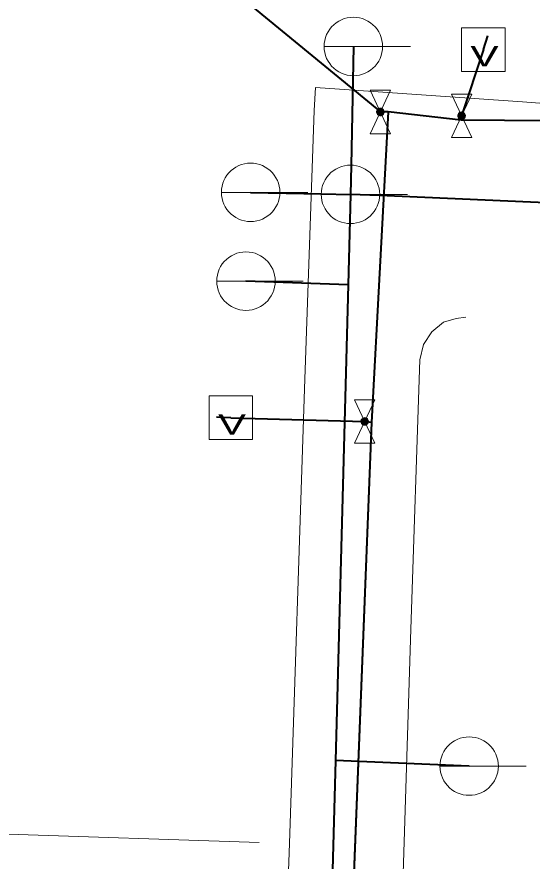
# Model space of a CAD drawing. Extents: x -968691 to -140888, y -1376050 to -879856.
# Drawn here: x -646127.69 to -646109.94, y -1062448.94 to -1062419.83 of the extents above; entities that cross this region are included whole.
import ezdxf
from ezdxf.enums import TextEntityAlignment as Align

# ---------------------------------------------------------------- set-up
doc = ezdxf.new("R2010")
doc.units = 0
doc.header["$LTSCALE"] = 4.8
doc.linetypes.add('DOTTED', pattern=[1.5, 0.3, -1.2])
doc.linetypes.add('LONG_DASHED', pattern=[7.5, 6, -1.5])
doc.layers.add('1', color=7, linetype='Continuous', lineweight=13)

msp = doc.modelspace()

# ---------------------------------------------------------------- hatches: boundary and pattern name
at = {"layer": '1'}
for points in [[(-646115.038, -1062423.11), (-646115.04, -1062423.086), (-646115.047, -1062423.063), (-646115.057, -1062423.041), (-646115.071, -1062423.022), (-646115.089, -1062423.005), (-646115.109, -1062422.992), (-646115.132, -1062422.983), (-646115.155, -1062422.979), (-646115.179, -1062422.978), (-646115.203, -1062422.982), (-646115.226, -1062422.99), (-646115.247, -1062423.002), (-646115.265, -1062423.018), (-646115.28, -1062423.037), (-646115.292, -1062423.058), (-646115.299, -1062423.081), (-646115.302, -1062423.105), (-646115.301, -1062423.129), (-646115.295, -1062423.152), (-646115.285, -1062423.174), (-646115.272, -1062423.194), (-646115.255, -1062423.211), (-646115.235, -1062423.225), (-646115.213, -1062423.235), (-646115.19, -1062423.241), (-646115.166, -1062423.242), (-646115.142, -1062423.239), (-646115.119, -1062423.232), (-646115.098, -1062423.221), (-646115.079, -1062423.206), (-646115.063, -1062423.187), (-646115.051, -1062423.167), (-646115.042, -1062423.144), (-646115.038, -1062423.12)], [(-646112.238, -1062423.24), (-646112.24, -1062423.216), (-646112.247, -1062423.193), (-646112.257, -1062423.171), (-646112.271, -1062423.152), (-646112.289, -1062423.135), (-646112.309, -1062423.122), (-646112.332, -1062423.113), (-646112.355, -1062423.109), (-646112.379, -1062423.108), (-646112.403, -1062423.112), (-646112.426, -1062423.12), (-646112.447, -1062423.132), (-646112.465, -1062423.148), (-646112.48, -1062423.167), (-646112.492, -1062423.188), (-646112.499, -1062423.211), (-646112.502, -1062423.235), (-646112.501, -1062423.259), (-646112.495, -1062423.282), (-646112.485, -1062423.304), (-646112.472, -1062423.324), (-646112.455, -1062423.341), (-646112.435, -1062423.355), (-646112.413, -1062423.365), (-646112.39, -1062423.371), (-646112.366, -1062423.372), (-646112.342, -1062423.369), (-646112.319, -1062423.362), (-646112.298, -1062423.351), (-646112.279, -1062423.336), (-646112.263, -1062423.317), (-646112.251, -1062423.297), (-646112.242, -1062423.274), (-646112.238, -1062423.25)], [(-646115.578, -1062433.78), (-646115.58, -1062433.756), (-646115.587, -1062433.733), (-646115.597, -1062433.711), (-646115.611, -1062433.692), (-646115.629, -1062433.675), (-646115.649, -1062433.662), (-646115.672, -1062433.653), (-646115.695, -1062433.649), (-646115.719, -1062433.648), (-646115.743, -1062433.652), (-646115.766, -1062433.66), (-646115.787, -1062433.672), (-646115.805, -1062433.688), (-646115.82, -1062433.707), (-646115.832, -1062433.728), (-646115.839, -1062433.751), (-646115.842, -1062433.775), (-646115.841, -1062433.799), (-646115.835, -1062433.822), (-646115.825, -1062433.844), (-646115.812, -1062433.864), (-646115.795, -1062433.881), (-646115.775, -1062433.895), (-646115.753, -1062433.905), (-646115.73, -1062433.911), (-646115.706, -1062433.912), (-646115.682, -1062433.909), (-646115.659, -1062433.902), (-646115.638, -1062433.891), (-646115.619, -1062433.876), (-646115.603, -1062433.857), (-646115.591, -1062433.837), (-646115.582, -1062433.814), (-646115.578, -1062433.79)]]:
    msp.add_hatch(color=256, dxfattribs=at).paths.add_polyline_path(points)

# ---------------------------------------------------------------- linework, layer by layer
at = {"layer": '1', "linetype": 'LONG_DASHED', "lineweight": 40}
for p, q in [((-646120.07, -1062419.07), (-646115.17, -1062423.11)), ((-646111.62, -1062420.96), (-646112.37, -1062423.24)), ((-646114.9, -1062423.11), (-646115.17, -1062423.11)), ((-646112.39, -1062423.39), (-646112.37, -1062423.24)), ((-646116.2, -1062425.95), (-646116.283, -1062429.074)), ((-646115.201, -1062425.99), (-646116.2, -1062425.95)), ((-646106.61, -1062426.36), (-646115.201, -1062425.99)), ((-646116.283, -1062429.074), (-646119.8, -1062428.94)), ((-646116.283, -1062429.074), (-646116.721, -1062445.47)), ((-646120.32, -1062433.65), (-646115.71, -1062433.78)), ((-646115.47, -1062433.81), (-646116.12, -1062450.33)), ((-646115.47, -1062433.81), (-646115.71, -1062433.78)), ((-646112.11, -1062445.66), (-646116.721, -1062445.47))]:
    msp.add_line(p, q, dxfattribs=at)
at = {"layer": '1'}
for p, q in [((-646120.07, -1062419.07), (-646115.17, -1062423.11)), ((-646111.62, -1062420.96), (-646111.464, -1062420.485)), ((-646117.108, -1062420.85), (-646114.132, -1062420.85)), ((-646111.62, -1062420.96), (-646112.37, -1062423.24)), ((-646117.453, -1062423.059), (-646117.41, -1062422.27)), ((-646117.782, -1062432.654), (-646117.453, -1062423.059)), ((-646114.9, -1062423.11), (-646115.17, -1062423.11)), ((-646112.39, -1062423.39), (-646112.37, -1062423.24)), ((-646120.648, -1062425.88), (-646117.672, -1062425.88)), ((-646117.208, -1062425.95), (-646114.232, -1062425.95)), ((-646115.201, -1062425.99), (-646116.2, -1062425.95)), ((-646106.61, -1062426.36), (-646115.201, -1062425.99)), ((-646120.808, -1062428.94), (-646117.832, -1062428.94)), ((-646116.283, -1062429.074), (-646119.8, -1062428.94)), ((-646118.301, -1062448.324), (-646117.782, -1062432.654)), ((-646120.32, -1062433.65), (-646120.82, -1062433.636)), ((-646120.32, -1062433.65), (-646115.71, -1062433.78)), ((-646115.47, -1062433.81), (-646115.71, -1062433.78)), ((-646112.11, -1062445.66), (-646116.721, -1062445.47)), ((-646113.118, -1062445.66), (-646110.142, -1062445.66)), ((-646119.342, -1062448.295), (-646144.199, -1062447.471)), ((-646118.635, -1062456.797), (-646118.301, -1062448.324))]:
    msp.add_line(p, q, dxfattribs=at)
at = {"layer": '1', "linetype": 'DOTTED', "lineweight": 40}
for p, q in [((-646111.62, -1062420.96), (-646111.464, -1062420.485)), ((-646120.32, -1062433.65), (-646120.82, -1062433.636))]:
    msp.add_line(p, q, dxfattribs=at)
at = {"layer": '1', "lineweight": 35}
for p, q in [((-646116.2, -1062425.95), (-646116.283, -1062429.074)), ((-646116.283, -1062429.074), (-646116.721, -1062445.47)), ((-646115.47, -1062433.81), (-646116.12, -1062450.33))]:
    msp.add_line(p, q, dxfattribs=at)
at = {"layer": '1'}
for points in [[(-646116.1, -1062419.842), (-646116.205, -1062419.848), (-646116.309, -1062419.864), (-646116.411, -1062419.892), (-646116.51, -1062419.93), (-646116.604, -1062419.977), (-646116.692, -1062420.035), (-646116.774, -1062420.101), (-646116.849, -1062420.176), (-646116.915, -1062420.258), (-646116.973, -1062420.346), (-646117.02, -1062420.44), (-646117.058, -1062420.539), (-646117.086, -1062420.641), (-646117.102, -1062420.745), (-646117.108, -1062420.85), (-646117.102, -1062420.955), (-646117.086, -1062421.06), (-646117.058, -1062421.162), (-646117.02, -1062421.26), (-646116.973, -1062421.354), (-646116.915, -1062421.443), (-646116.849, -1062421.525), (-646116.774, -1062421.599), (-646116.692, -1062421.665), (-646116.604, -1062421.723), (-646116.51, -1062421.771), (-646116.411, -1062421.809), (-646116.309, -1062421.836), (-646116.205, -1062421.852), (-646116.1, -1062421.858), (-646115.995, -1062421.852), (-646115.89, -1062421.836), (-646115.788, -1062421.809), (-646115.69, -1062421.771), (-646115.596, -1062421.723), (-646115.507, -1062421.665), (-646115.425, -1062421.599), (-646115.351, -1062421.525), (-646115.285, -1062421.443), (-646115.227, -1062421.354), (-646115.179, -1062421.26), (-646115.141, -1062421.162), (-646115.114, -1062421.06), (-646115.098, -1062420.955), (-646115.092, -1062420.85), (-646115.098, -1062420.745), (-646115.114, -1062420.641), (-646115.141, -1062420.539), (-646115.179, -1062420.44), (-646115.227, -1062420.346), (-646115.285, -1062420.258), (-646115.351, -1062420.176), (-646115.425, -1062420.101), (-646115.507, -1062420.035), (-646115.596, -1062419.977), (-646115.69, -1062419.93), (-646115.788, -1062419.892), (-646115.89, -1062419.864), (-646115.995, -1062419.848)], [(-646112.37, -1062421.71), (-646110.87, -1062421.71), (-646110.87, -1062420.21), (-646112.37, -1062420.21)], [(-646115.52, -1062422.36), (-646114.82, -1062422.36), (-646115.52, -1062423.86), (-646114.82, -1062423.86)], [(-646112.72, -1062422.49), (-646112.02, -1062422.49), (-646112.72, -1062423.99), (-646112.02, -1062423.99)], [(-646115.038, -1062423.11), (-646115.04, -1062423.086), (-646115.047, -1062423.063), (-646115.057, -1062423.041), (-646115.071, -1062423.022), (-646115.089, -1062423.005), (-646115.109, -1062422.992), (-646115.132, -1062422.983), (-646115.155, -1062422.979), (-646115.179, -1062422.978), (-646115.203, -1062422.982), (-646115.226, -1062422.99), (-646115.247, -1062423.002), (-646115.265, -1062423.018), (-646115.28, -1062423.037), (-646115.292, -1062423.058), (-646115.299, -1062423.081), (-646115.302, -1062423.105), (-646115.301, -1062423.129), (-646115.295, -1062423.152), (-646115.285, -1062423.174), (-646115.272, -1062423.194), (-646115.255, -1062423.211), (-646115.235, -1062423.225), (-646115.213, -1062423.235), (-646115.19, -1062423.241), (-646115.166, -1062423.242), (-646115.142, -1062423.239), (-646115.119, -1062423.232), (-646115.098, -1062423.221), (-646115.079, -1062423.206), (-646115.063, -1062423.187), (-646115.051, -1062423.167), (-646115.042, -1062423.144), (-646115.038, -1062423.12)], [(-646112.238, -1062423.24), (-646112.24, -1062423.216), (-646112.247, -1062423.193), (-646112.257, -1062423.171), (-646112.271, -1062423.152), (-646112.289, -1062423.135), (-646112.309, -1062423.122), (-646112.332, -1062423.113), (-646112.355, -1062423.109), (-646112.379, -1062423.108), (-646112.403, -1062423.112), (-646112.426, -1062423.12), (-646112.447, -1062423.132), (-646112.465, -1062423.148), (-646112.48, -1062423.167), (-646112.492, -1062423.188), (-646112.499, -1062423.211), (-646112.502, -1062423.235), (-646112.501, -1062423.259), (-646112.495, -1062423.282), (-646112.485, -1062423.304), (-646112.472, -1062423.324), (-646112.455, -1062423.341), (-646112.435, -1062423.355), (-646112.413, -1062423.365), (-646112.39, -1062423.371), (-646112.366, -1062423.372), (-646112.342, -1062423.369), (-646112.319, -1062423.362), (-646112.298, -1062423.351), (-646112.279, -1062423.336), (-646112.263, -1062423.317), (-646112.251, -1062423.297), (-646112.242, -1062423.274), (-646112.238, -1062423.25)], [(-646119.64, -1062424.872), (-646119.745, -1062424.878), (-646119.849, -1062424.894), (-646119.951, -1062424.922), (-646120.05, -1062424.96), (-646120.144, -1062425.007), (-646120.232, -1062425.065), (-646120.314, -1062425.131), (-646120.389, -1062425.206), (-646120.455, -1062425.288), (-646120.513, -1062425.376), (-646120.56, -1062425.47), (-646120.598, -1062425.569), (-646120.626, -1062425.671), (-646120.642, -1062425.775), (-646120.648, -1062425.88), (-646120.642, -1062425.985), (-646120.626, -1062426.09), (-646120.598, -1062426.192), (-646120.56, -1062426.29), (-646120.513, -1062426.384), (-646120.455, -1062426.473), (-646120.389, -1062426.555), (-646120.314, -1062426.629), (-646120.232, -1062426.695), (-646120.144, -1062426.753), (-646120.05, -1062426.801), (-646119.951, -1062426.839), (-646119.849, -1062426.866), (-646119.745, -1062426.882), (-646119.64, -1062426.888), (-646119.535, -1062426.882), (-646119.43, -1062426.866), (-646119.328, -1062426.839), (-646119.23, -1062426.801), (-646119.136, -1062426.753), (-646119.047, -1062426.695), (-646118.965, -1062426.629), (-646118.891, -1062426.555), (-646118.825, -1062426.473), (-646118.767, -1062426.384), (-646118.719, -1062426.29), (-646118.681, -1062426.192), (-646118.654, -1062426.09), (-646118.638, -1062425.985), (-646118.632, -1062425.88), (-646118.638, -1062425.775), (-646118.654, -1062425.671), (-646118.681, -1062425.569), (-646118.719, -1062425.47), (-646118.767, -1062425.376), (-646118.825, -1062425.288), (-646118.891, -1062425.206), (-646118.965, -1062425.131), (-646119.047, -1062425.065), (-646119.136, -1062425.007), (-646119.23, -1062424.96), (-646119.328, -1062424.922), (-646119.43, -1062424.894), (-646119.535, -1062424.878)], [(-646116.2, -1062424.942), (-646116.305, -1062424.948), (-646116.409, -1062424.964), (-646116.511, -1062424.992), (-646116.61, -1062425.03), (-646116.704, -1062425.077), (-646116.792, -1062425.135), (-646116.874, -1062425.201), (-646116.949, -1062425.276), (-646117.015, -1062425.358), (-646117.073, -1062425.446), (-646117.12, -1062425.54), (-646117.158, -1062425.639), (-646117.186, -1062425.741), (-646117.202, -1062425.845), (-646117.208, -1062425.95), (-646117.202, -1062426.055), (-646117.186, -1062426.16), (-646117.158, -1062426.262), (-646117.12, -1062426.36), (-646117.073, -1062426.454), (-646117.015, -1062426.543), (-646116.949, -1062426.625), (-646116.874, -1062426.699), (-646116.792, -1062426.765), (-646116.704, -1062426.823), (-646116.61, -1062426.871), (-646116.511, -1062426.909), (-646116.409, -1062426.936), (-646116.305, -1062426.952), (-646116.2, -1062426.958), (-646116.095, -1062426.952), (-646115.99, -1062426.936), (-646115.888, -1062426.909), (-646115.79, -1062426.871), (-646115.696, -1062426.823), (-646115.607, -1062426.765), (-646115.525, -1062426.699), (-646115.451, -1062426.625), (-646115.385, -1062426.543), (-646115.327, -1062426.454), (-646115.279, -1062426.36), (-646115.241, -1062426.262), (-646115.214, -1062426.16), (-646115.198, -1062426.055), (-646115.192, -1062425.95), (-646115.198, -1062425.845), (-646115.214, -1062425.741), (-646115.241, -1062425.639), (-646115.279, -1062425.54), (-646115.327, -1062425.446), (-646115.385, -1062425.358), (-646115.451, -1062425.276), (-646115.525, -1062425.201), (-646115.607, -1062425.135), (-646115.696, -1062425.077), (-646115.79, -1062425.03), (-646115.888, -1062424.992), (-646115.99, -1062424.964), (-646116.095, -1062424.948)], [(-646119.8, -1062427.932), (-646119.905, -1062427.938), (-646120.009, -1062427.954), (-646120.111, -1062427.982), (-646120.21, -1062428.02), (-646120.304, -1062428.067), (-646120.392, -1062428.125), (-646120.474, -1062428.191), (-646120.549, -1062428.266), (-646120.615, -1062428.348), (-646120.673, -1062428.436), (-646120.72, -1062428.53), (-646120.758, -1062428.629), (-646120.786, -1062428.731), (-646120.802, -1062428.835), (-646120.808, -1062428.94), (-646120.802, -1062429.045), (-646120.786, -1062429.15), (-646120.758, -1062429.252), (-646120.72, -1062429.35), (-646120.673, -1062429.444), (-646120.615, -1062429.533), (-646120.549, -1062429.615), (-646120.474, -1062429.689), (-646120.392, -1062429.755), (-646120.304, -1062429.813), (-646120.21, -1062429.861), (-646120.111, -1062429.899), (-646120.009, -1062429.926), (-646119.905, -1062429.942), (-646119.8, -1062429.948), (-646119.695, -1062429.942), (-646119.59, -1062429.926), (-646119.488, -1062429.899), (-646119.39, -1062429.861), (-646119.296, -1062429.813), (-646119.207, -1062429.755), (-646119.125, -1062429.689), (-646119.051, -1062429.615), (-646118.985, -1062429.533), (-646118.927, -1062429.444), (-646118.879, -1062429.35), (-646118.841, -1062429.252), (-646118.814, -1062429.15), (-646118.798, -1062429.045), (-646118.792, -1062428.94), (-646118.798, -1062428.835), (-646118.814, -1062428.731), (-646118.841, -1062428.629), (-646118.879, -1062428.53), (-646118.927, -1062428.436), (-646118.985, -1062428.348), (-646119.051, -1062428.266), (-646119.125, -1062428.191), (-646119.207, -1062428.125), (-646119.296, -1062428.067), (-646119.39, -1062428.02), (-646119.488, -1062427.982), (-646119.59, -1062427.954), (-646119.695, -1062427.938)], [(-646121.07, -1062434.4), (-646119.57, -1062434.4), (-646119.57, -1062432.9), (-646121.07, -1062432.9)], [(-646116.06, -1062433.03), (-646115.36, -1062433.03), (-646116.06, -1062434.53), (-646115.36, -1062434.53)], [(-646115.578, -1062433.78), (-646115.58, -1062433.756), (-646115.587, -1062433.733), (-646115.597, -1062433.711), (-646115.611, -1062433.692), (-646115.629, -1062433.675), (-646115.649, -1062433.662), (-646115.672, -1062433.653), (-646115.695, -1062433.649), (-646115.719, -1062433.648), (-646115.743, -1062433.652), (-646115.766, -1062433.66), (-646115.787, -1062433.672), (-646115.805, -1062433.688), (-646115.82, -1062433.707), (-646115.832, -1062433.728), (-646115.839, -1062433.751), (-646115.842, -1062433.775), (-646115.841, -1062433.799), (-646115.835, -1062433.822), (-646115.825, -1062433.844), (-646115.812, -1062433.864), (-646115.795, -1062433.881), (-646115.775, -1062433.895), (-646115.753, -1062433.905), (-646115.73, -1062433.911), (-646115.706, -1062433.912), (-646115.682, -1062433.909), (-646115.659, -1062433.902), (-646115.638, -1062433.891), (-646115.619, -1062433.876), (-646115.603, -1062433.857), (-646115.591, -1062433.837), (-646115.582, -1062433.814), (-646115.578, -1062433.79)], [(-646112.11, -1062444.652), (-646112.215, -1062444.658), (-646112.319, -1062444.674), (-646112.421, -1062444.702), (-646112.52, -1062444.74), (-646112.614, -1062444.787), (-646112.702, -1062444.845), (-646112.784, -1062444.911), (-646112.859, -1062444.986), (-646112.925, -1062445.068), (-646112.983, -1062445.156), (-646113.03, -1062445.25), (-646113.068, -1062445.349), (-646113.096, -1062445.451), (-646113.112, -1062445.555), (-646113.118, -1062445.66), (-646113.112, -1062445.765), (-646113.096, -1062445.87), (-646113.068, -1062445.972), (-646113.03, -1062446.07), (-646112.983, -1062446.164), (-646112.925, -1062446.253), (-646112.859, -1062446.335), (-646112.784, -1062446.409), (-646112.702, -1062446.475), (-646112.614, -1062446.533), (-646112.52, -1062446.581), (-646112.421, -1062446.619), (-646112.319, -1062446.646), (-646112.215, -1062446.662), (-646112.11, -1062446.668), (-646112.005, -1062446.662), (-646111.9, -1062446.646), (-646111.798, -1062446.619), (-646111.7, -1062446.581), (-646111.606, -1062446.533), (-646111.517, -1062446.475), (-646111.435, -1062446.409), (-646111.361, -1062446.335), (-646111.295, -1062446.253), (-646111.237, -1062446.164), (-646111.189, -1062446.07), (-646111.151, -1062445.972), (-646111.124, -1062445.87), (-646111.108, -1062445.765), (-646111.102, -1062445.66), (-646111.108, -1062445.555), (-646111.124, -1062445.451), (-646111.151, -1062445.349), (-646111.189, -1062445.25), (-646111.237, -1062445.156), (-646111.295, -1062445.068), (-646111.361, -1062444.986), (-646111.435, -1062444.911), (-646111.517, -1062444.845), (-646111.606, -1062444.787), (-646111.7, -1062444.74), (-646111.798, -1062444.702), (-646111.9, -1062444.674), (-646112.005, -1062444.658)]]:
    msp.add_lwpolyline(points, close=True, dxfattribs=at)
at = {"layer": '1', "linetype": 'LONG_DASHED', "lineweight": 40}
for points in [[(-646116.1, -1062420.85), (-646116.179, -1062424.95), (-646116.2, -1062425.95)], [(-646108.14, -1062423.8), (-646108.71, -1062423.68), (-646109.02, -1062423.43), (-646109.4, -1062423.42), (-646112.39, -1062423.39), (-646114.9, -1062423.11), (-646115.47, -1062433.81)], [(-646119.64, -1062425.88), (-646117.2, -1062425.928), (-646116.2, -1062425.95)], [(-646116.721, -1062445.47), (-646117.06, -1062458.18), (-646117.174, -1062466.412), (-646117.219, -1062469.7), (-646117.228, -1062470.338), (-646117.282, -1062474.217)]]:
    msp.add_lwpolyline(points, dxfattribs=at)
at = {"layer": '1'}
for points in [[(-646116.1, -1062420.85), (-646116.179, -1062424.95), (-646116.2, -1062425.95)], [(-646117.41, -1062422.27), (-646110.271, -1062422.754), (-646107.76, -1062422.95)], [(-646119.64, -1062425.88), (-646117.2, -1062425.928), (-646116.2, -1062425.95)], [(-646112.226, -1062430.181), (-646112.562, -1062430.235), (-646112.99, -1062430.36), (-646113.4, -1062430.69), (-646113.68, -1062431.12), (-646113.81, -1062431.66)], [(-646113.81, -1062431.66), (-646114.114, -1062440.939), (-646114.71, -1062459.64)]]:
    msp.add_lwpolyline(points, dxfattribs=at)
at = {"layer": '1', "lineweight": 35}
for points in [[(-646108.14, -1062423.8), (-646108.71, -1062423.68), (-646109.02, -1062423.43), (-646109.4, -1062423.42), (-646112.39, -1062423.39), (-646114.9, -1062423.11), (-646115.47, -1062433.81)], [(-646116.721, -1062445.47), (-646117.06, -1062458.18), (-646117.174, -1062466.412), (-646117.219, -1062469.7), (-646117.228, -1062470.338), (-646117.282, -1062474.217)]]:
    msp.add_lwpolyline(points, dxfattribs=at)

# ---------------------------------------------------------------- texts
at = {"layer": '1', "width": 1.55}
for p in [(-646111.581, -1062421.539), (-646120.281, -1062434.229)]:
    msp.add_text('V', height=0.7, dxfattribs=at).set_placement(p, align=Align.CENTER)

doc.saveas('drawing.dxf')
